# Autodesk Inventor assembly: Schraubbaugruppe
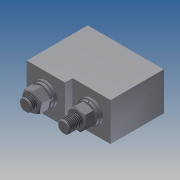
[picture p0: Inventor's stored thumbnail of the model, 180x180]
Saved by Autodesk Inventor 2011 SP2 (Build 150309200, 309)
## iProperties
Created: 2012-06
Part Number: Schraubbaugruppe
Document SubType Name: Assembly
Designer: JRE
Author: JRE
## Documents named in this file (3)
- E:\Users\jre\Documents\Inventor\Test\Schraubbaugruppe.iam
- E:\Users\jre\Documents\Inventor\Test\Klotz_1.ipt
- E:\Users\jre\Documents\Inventor\Test\Schraub_Gruppe.iam
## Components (3 placed, 2 different names)
1. Klotz_1:1 — Einfügen:1, Einfügen:2, Einfügen:3
2. Schraub_Gruppe:1 [sub-assembly] — Einfügen:2
3. Schraub_Gruppe:2 [sub-assembly] — Einfügen:1, Einfügen:3
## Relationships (3: Insert 3)
- Einfügen:1 [Insert]: Klotz_1:1 ↔ Schraub_Gruppe:2
- Einfügen:2 [Insert]: Klotz_1:1 ↔ Schraub_Gruppe:1
- Einfügen:3 [Insert]: Klotz_1:1 ↔ Schraub_Gruppe:2
